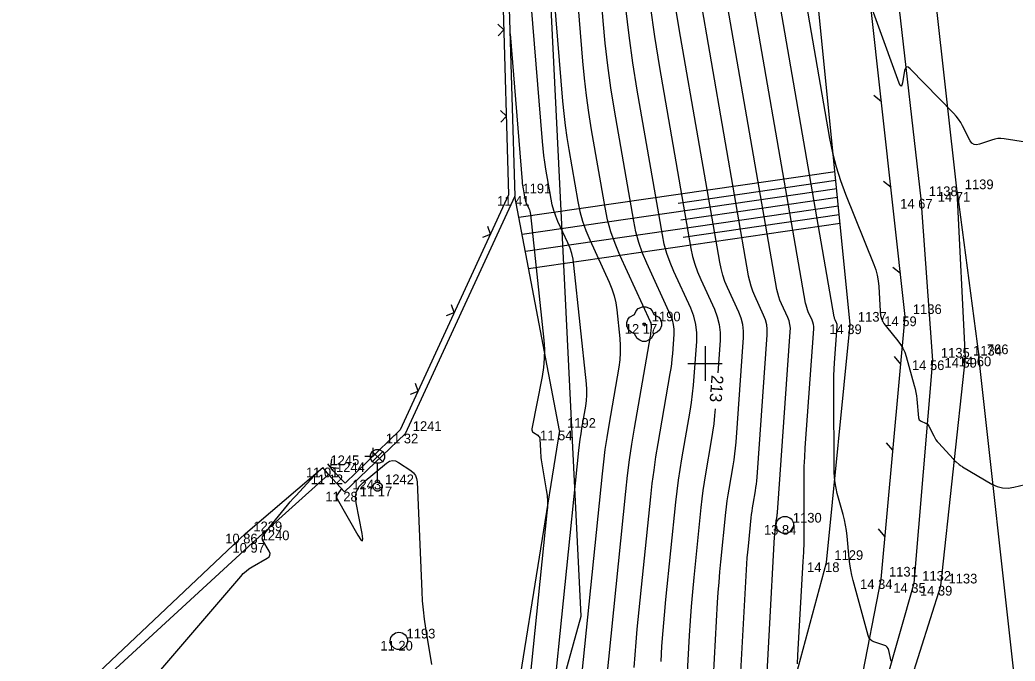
# Model space of a CAD drawing. Extents: x -711234 to -710007, y -1026313 to -1025448.
# Drawn here: x -710944.81 to -710916.03, y -1025833.6 to -1025815.07 of the extents above; entities that cross this region are included whole.
import ezdxf

# ---------------------------------------------------------------- set-up
doc = ezdxf.new("R2010")
doc.units = 0
for name, color, linetype in [('Ex_Contour Labels', 7, 'Continuous'), ('Ex_Major Contours', 7, 'Continuous'), ('Ex_Minor Contours', 7, 'Continuous'), ('Z_body', 7, 'Continuous'), ('Z_body_cisla', 7, 'Continuous'), ('Z_body_vysky_redukovane', 7, 'Continuous'), ('Z_hektometricka_sit', 7, 'Continuous'), ('Z_hrany_paty', 7, 'Continuous'), ('Z_katastr_hranice', 7, 'Continuous'), ('Z_komunikace', 7, 'Continuous'), ('Z_obruba', 7, 'Continuous'), ('Z_ploty', 7, 'Continuous'), ('Z_ploty_znacky', 7, 'Continuous'), ('Z_site_vo_znaky', 7, 'Continuous'), ('Z_svodidla', 7, 'Continuous'), ('Z_svodidla_znacky', 7, 'Continuous'), ('Z_technicke_srafy', 7, 'Continuous'), ('Z_vdz25_plna', 7, 'Continuous'), ('Z_vdz25_prerusovana', 7, 'Continuous'), ('Z_zelen_jednotliva', 7, 'Continuous')]:
    doc.layers.add(name, color=color, linetype=linetype)

# ---------------------------------------------------------------- blocks, each defined once
blk = doc.blocks.new('POINT_DISPLAY')
blk.add_line((0, 0), (0, 0))
blk = doc.blocks.new('Z10001')
blk.add_circle((0, 0), 0.25)
blk = doc.blocks.new('Z24')
for p, q in [((-0.28, 0.28), (-0.23, 0.38)), ((-0.23, 0.38), (-0.17, 0.45)), ((-0.17, 0.45), (-0.05, 0.5)), ((-0.05, 0.5), (0.05, 0.5)), ((0.05, 0.5), (0.17, 0.45)), ((0.17, 0.45), (0.23, 0.38)), ((0.23, 0.38), (0.28, 0.28)), ((-0.5, 0.05), (-0.47, 0.13)), ((-0.5, -0.05), (-0.5, 0.05)), ((-0.47, 0.13), (-0.42, 0.2)), ((-0.42, 0.2), (-0.28, 0.28)), ((-0.03, -0.03), (-0.03, 0.03)), ((-0.03, 0.03), (0.03, 0.03)), ((0.03, 0.03), (0.03, -0.03)), ((0.28, 0.28), (0.42, 0.2)), ((0.42, 0.2), (0.47, 0.13)), ((0.47, 0.13), (0.5, 0.05)), ((0.5, 0.05), (0.5, -0.05)), ((-0.45, -0.17), (-0.5, -0.05)), ((-0.38, -0.23), (-0.45, -0.17)), ((-0.28, -0.28), (-0.38, -0.23)), ((-0.2, -0.42), (-0.28, -0.28)), ((0.03, -0.03), (-0.03, -0.03)), ((0.28, -0.28), (0.2, -0.42)), ((0.38, -0.23), (0.28, -0.28)), ((0.45, -0.17), (0.38, -0.23)), ((0.5, -0.05), (0.45, -0.17)), ((-0.13, -0.47), (-0.2, -0.42)), ((-0.05, -0.5), (-0.13, -0.47)), ((0.05, -0.5), (-0.05, -0.5)), ((0.13, -0.47), (0.05, -0.5)), ((0.2, -0.42), (0.13, -0.47))]:
    blk.add_line(p, q)
blk = doc.blocks.new('Z34')
for p, q in [((-0.2, 0.93), (-0.15, 1.02)), ((-0.2, 0.82), (-0.2, 0.93)), ((-0.15, 1.02), (-0.05, 1.07)), ((0.15, 0.72), (-0.15, 1.02)), ((0.15, 1.02), (-0.15, 0.72)), ((-0.05, 1.07), (0.05, 1.07)), ((0.05, 1.07), (0.15, 1.02)), ((0.15, 1.02), (0.2, 0.93)), ((0.2, 0.93), (0.2, 0.82)), ((-0.15, 0.72), (-0.2, 0.82)), ((-0.05, 0.68), (-0.15, 0.72)), ((0.05, 0.68), (-0.05, 0.68)), ((0, 0.13), (0, 0.68)), ((0.15, 0.72), (0.05, 0.68)), ((0.2, 0.82), (0.15, 0.72)), ((-0.13, 0.03), (-0.1, 0.08)), ((-0.13, -0.03), (-0.13, 0.03)), ((-0.1, 0.08), (-0.08, 0.1)), ((-0.08, 0.1), (-0.03, 0.13)), ((-0.03, 0.13), (0.03, 0.13)), ((0.03, 0.13), (0.08, 0.1)), ((0.08, 0.1), (0.1, 0.08)), ((0.1, 0.08), (0.13, 0.03)), ((0.13, 0.03), (0.13, -0.03)), ((-0.1, -0.08), (-0.13, -0.03)), ((-0.08, -0.1), (-0.1, -0.08)), ((-0.03, -0.13), (-0.08, -0.1)), ((0.03, -0.13), (-0.03, -0.13)), ((0.08, -0.1), (0.03, -0.13)), ((0.1, -0.08), (0.08, -0.1)), ((0.13, -0.03), (0.1, -0.08))]:
    blk.add_line(p, q)
blk = doc.blocks.new('Z212')
for p, q in [((-0.17, 0.17), (0, 0)), ((0, 0), (0.17, 0.17))]:
    blk.add_line(p, q)
blk = doc.blocks.new('Z529')
blk.add_line((0, 0), (0.2, 0.2))

msp = doc.modelspace()

# ---------------------------------------------------------------- linework, layer by layer
at = {"layer": 'Ex_Major Contours'}
for points in [[(-710929.638, -1025811.052), (-710929.118, -1025817.417), (-710929.086, -1025817.767), (-710929.045, -1025818.117), (-710928.997, -1025818.465), (-710928.941, -1025818.813), (-710928.68, -1025820.315), (-710928.621, -1025820.602), (-710928.543, -1025820.883), (-710928.448, -1025821.159), (-710928.334, -1025821.429), (-710927.771, -1025822.653), (-710927.692, -1025822.845), (-710927.629, -1025823.041), (-710927.583, -1025823.242), (-710927.553, -1025823.447), (-710927.465, -1025824.276), (-710927.45, -1025824.484), (-710927.45, -1025824.69), (-710927.464, -1025824.896), (-710927.492, -1025825.102), (-710927.785, -1025826.787), (-710927.842, -1025827.137), (-710927.894, -1025827.488), (-710927.939, -1025827.839), (-710927.978, -1025828.192), (-710928.611, -1025834.404)], [(-710922.323, -1025833.681), (-710922.318, -1025833.429), (-710922.158, -1025830.726), (-710922.144, -1025830.452), (-710922.134, -1025830.178), (-710922.129, -1025829.904), (-710922.129, -1025829.629), (-710922.136, -1025828.532), (-710922.136, -1025828.257), (-710922.129, -1025827.983), (-710922.118, -1025827.709), (-710922.101, -1025827.435), (-710921.856, -1025824.001), (-710921.856, -1025823.935), (-710921.863, -1025823.871), (-710921.879, -1025823.809), (-710921.903, -1025823.747), (-710922.014, -1025823.505), (-710922.04, -1025823.444), (-710922.061, -1025823.382), (-710922.079, -1025823.318), (-710922.092, -1025823.253), (-710924.05, -1025811.969)], [(-710926.582, -1025814.654), (-710926.458, -1025815.549), (-710926.313, -1025816.441), (-710925.406, -1025821.672), (-710925.358, -1025821.903), (-710925.295, -1025822.13), (-710925.218, -1025822.353), (-710925.126, -1025822.571), (-710924.73, -1025823.433), (-710924.645, -1025823.651), (-710924.59, -1025823.874), (-710924.563, -1025824.103), (-710924.565, -1025824.337), (-710924.632, -1025825.268)], [(-710924.707, -1025826.315), (-710924.723, -1025826.504), (-710924.749, -1025826.746), (-710924.782, -1025826.988), (-710924.821, -1025827.229), (-710924.988, -1025828.192), (-710925.027, -1025828.433), (-710925.063, -1025828.674), (-710925.094, -1025828.916), (-710925.121, -1025829.159), (-710925.327, -1025831.184), (-710925.367, -1025831.603), (-710925.403, -1025832.022), (-710925.433, -1025832.442), (-710925.459, -1025832.861), (-710925.596, -1025835.349)], [(-710941.945, -1025835.27), (-710938.425, -1025831.155), (-710938.352, -1025831.076), (-710938.272, -1025831.004), (-710938.187, -1025830.939), (-710938.095, -1025830.882), (-710937.657, -1025830.632), (-710937.605, -1025830.592), (-710937.579, -1025830.545), (-710937.578, -1025830.492), (-710937.602, -1025830.431), (-710937.784, -1025830.114), (-710937.798, -1025830.081), (-710937.802, -1025830.048), (-710937.795, -1025830.015), (-710937.777, -1025829.984), (-710937.687, -1025829.857), (-710937.664, -1025829.826), (-710937.641, -1025829.795), (-710937.617, -1025829.764), (-710937.593, -1025829.734), (-710937.159, -1025829.198), (-710937.077, -1025829.099), (-710936.995, -1025829.002), (-710936.91, -1025828.906), (-710936.824, -1025828.812), (-710936.199, -1025828.137)]]:
    msp.add_lwpolyline(points, dxfattribs=at)
at = {"layer": 'Ex_Minor Contours'}
for points in [[(-710929.438, -1025835.264), (-710928.648, -1025827.511), (-710928.63, -1025827.35), (-710928.609, -1025827.19), (-710928.586, -1025827.03), (-710928.559, -1025826.87), (-710928.449, -1025826.232), (-710928.427, -1025826.073), (-710928.416, -1025825.913), (-710928.416, -1025825.752), (-710928.427, -1025825.591), (-710928.791, -1025822.152), (-710928.816, -1025821.986), (-710928.853, -1025821.823), (-710928.904, -1025821.663), (-710928.968, -1025821.507), (-710929.252, -1025820.891), (-710929.317, -1025820.736), (-710929.372, -1025820.577), (-710929.417, -1025820.415), (-710929.451, -1025820.249), (-710929.601, -1025819.384), (-710929.634, -1025819.183), (-710929.662, -1025818.983), (-710929.685, -1025818.781), (-710929.704, -1025818.579), (-710930.675, -1025806.688)], [(-710927.812, -1025833.833), (-710927.784, -1025833.545), (-710927.291, -1025828.703), (-710927.24, -1025828.243), (-710927.181, -1025827.785), (-710927.114, -1025827.328), (-710927.039, -1025826.872), (-710926.577, -1025824.207), (-710926.571, -1025824.173), (-710926.567, -1025824.138), (-710926.563, -1025824.104), (-710926.56, -1025824.069), (-710926.55, -1025823.93), (-710926.55, -1025823.895), (-710926.554, -1025823.862), (-710926.562, -1025823.829), (-710926.574, -1025823.797), (-710927.461, -1025821.869), (-710927.602, -1025821.534), (-710927.721, -1025821.192), (-710927.817, -1025820.842), (-710927.891, -1025820.486), (-710928.28, -1025818.242), (-710928.36, -1025817.747), (-710928.429, -1025817.251), (-710928.487, -1025816.753), (-710928.533, -1025816.254), (-710929.27, -1025807.237)], [(-710927.051, -1025833.791), (-710927.024, -1025833.422), (-710926.993, -1025833.053), (-710926.958, -1025832.685), (-710926.568, -1025828.855), (-710926.525, -1025828.468), (-710926.475, -1025828.081), (-710926.419, -1025827.696), (-710926.355, -1025827.312), (-710926.005, -1025825.291), (-710925.982, -1025825.149), (-710925.963, -1025825.007), (-710925.947, -1025824.865), (-710925.935, -1025824.721), (-710925.894, -1025824.148), (-710925.893, -1025824.006), (-710925.909, -1025823.868), (-710925.943, -1025823.733), (-710925.994, -1025823.6), (-710926.683, -1025822.103), (-710926.807, -1025821.807), (-710926.912, -1025821.505), (-710926.997, -1025821.196), (-710927.062, -1025820.881), (-710927.619, -1025817.671), (-710927.723, -1025817.029), (-710927.813, -1025816.385), (-710927.887, -1025815.74), (-710927.948, -1025815.092), (-710928.567, -1025807.512)], [(-710922.918, -1025809.733), (-710921.399, -1025818.492), (-710921.316, -1025818.904), (-710921.212, -1025819.309), (-710921.087, -1025819.709), (-710920.94, -1025820.102), (-710920.116, -1025822.142), (-710920.062, -1025822.295), (-710920.021, -1025822.45), (-710919.993, -1025822.608), (-710919.977, -1025822.769), (-710919.939, -1025823.483), (-710919.923, -1025823.609), (-710919.887, -1025823.728), (-710919.832, -1025823.84), (-710919.758, -1025823.943), (-710919.422, -1025824.343), (-710919.344, -1025824.446), (-710919.278, -1025824.556), (-710919.225, -1025824.672), (-710919.184, -1025824.795), (-710918.95, -1025825.637), (-710918.925, -1025825.735), (-710918.905, -1025825.834), (-710918.889, -1025825.933), (-710918.877, -1025826.033), (-710918.826, -1025826.567), (-710918.819, -1025826.599), (-710918.805, -1025826.626), (-710918.784, -1025826.648), (-710918.755, -1025826.665), (-710918.628, -1025826.722), (-710918.598, -1025826.738), (-710918.572, -1025826.758), (-710918.55, -1025826.783), (-710918.533, -1025826.812), (-710918.388, -1025827.096), (-710918.356, -1025827.152), (-710918.322, -1025827.206), (-710918.284, -1025827.258), (-710918.242, -1025827.307), (-710917.83, -1025827.761), (-710917.809, -1025827.783), (-710917.788, -1025827.804), (-710917.766, -1025827.824), (-710917.743, -1025827.843), (-710917.65, -1025827.919), (-710917.627, -1025827.938), (-710917.602, -1025827.955), (-710917.578, -1025827.972), (-710917.552, -1025827.987), (-710916.705, -1025828.485), (-710916.552, -1025828.557), (-710916.395, -1025828.597), (-710916.233, -1025828.605), (-710916.067, -1025828.58), (-710915.084, -1025828.345)], [(-710910.438, -1025819.427), (-710916.352, -1025818.505), (-710916.444, -1025818.496), (-710916.535, -1025818.499), (-710916.625, -1025818.513), (-710916.714, -1025818.538), (-710917.068, -1025818.662), (-710917.151, -1025818.678), (-710917.222, -1025818.666), (-710917.282, -1025818.626), (-710917.331, -1025818.557), (-710917.553, -1025818.125), (-710917.608, -1025818.028), (-710917.669, -1025817.935), (-710917.737, -1025817.848), (-710917.812, -1025817.765), (-710919.067, -1025816.479), (-710919.125, -1025816.433), (-710919.171, -1025816.426), (-710919.205, -1025816.458), (-710919.228, -1025816.528), (-710919.293, -1025816.887), (-710919.311, -1025816.955), (-710919.333, -1025816.979), (-710919.359, -1025816.959), (-710919.388, -1025816.895), (-710921.851, -1025810.091)], [(-710919.617, -1025833.609), (-710919.686, -1025833.299), (-710919.705, -1025833.244), (-710919.735, -1025833.199), (-710919.776, -1025833.165), (-710919.829, -1025833.141), (-710920.116, -1025833.045), (-710920.177, -1025833.017), (-710920.226, -1025832.978), (-710920.263, -1025832.927), (-710920.287, -1025832.864), (-710920.715, -1025831.277), (-710920.753, -1025831.12), (-710920.785, -1025830.962), (-710920.811, -1025830.803), (-710920.83, -1025830.642), (-710920.892, -1025829.989), (-710920.911, -1025829.832), (-710920.936, -1025829.677), (-710920.968, -1025829.523), (-710921.007, -1025829.37), (-710921.176, -1025828.761), (-710921.213, -1025828.608), (-710921.239, -1025828.454), (-710921.256, -1025828.298), (-710921.262, -1025828.141), (-710921.279, -1025825.717), (-710921.278, -1025825.532), (-710921.274, -1025825.347), (-710921.266, -1025825.162), (-710921.255, -1025824.977), (-710921.179, -1025823.917), (-710921.179, -1025823.893), (-710921.182, -1025823.87), (-710921.187, -1025823.848), (-710921.196, -1025823.826), (-710921.236, -1025823.739), (-710921.245, -1025823.717), (-710921.253, -1025823.695), (-710921.259, -1025823.672), (-710921.264, -1025823.649), (-710923.484, -1025810.851)], [(-710923.283, -1025835.371), (-710922.987, -1025830.012), (-710922.984, -1025829.967), (-710922.981, -1025829.922), (-710922.977, -1025829.877), (-710922.973, -1025829.832), (-710922.95, -1025829.615), (-710922.948, -1025829.589), (-710922.944, -1025829.563), (-710922.94, -1025829.537), (-710922.936, -1025829.512), (-710922.918, -1025829.408), (-710922.914, -1025829.383), (-710922.911, -1025829.357), (-710922.908, -1025829.331), (-710922.906, -1025829.305), (-710922.534, -1025824.085), (-710922.533, -1025823.977), (-710922.545, -1025823.872), (-710922.57, -1025823.769), (-710922.609, -1025823.669), (-710922.792, -1025823.272), (-710922.834, -1025823.171), (-710922.87, -1025823.069), (-710922.899, -1025822.965), (-710922.921, -1025822.858), (-710924.616, -1025813.087)], [(-710925.182, -1025814.205), (-710923.749, -1025822.463), (-710923.718, -1025822.611), (-710923.678, -1025822.756), (-710923.629, -1025822.899), (-710923.57, -1025823.038), (-710923.316, -1025823.59), (-710923.262, -1025823.73), (-710923.226, -1025823.873), (-710923.209, -1025824.019), (-710923.211, -1025824.169), (-710923.505, -1025828.29), (-710923.513, -1025828.388), (-710923.524, -1025828.487), (-710923.537, -1025828.584), (-710923.552, -1025828.682), (-710923.62, -1025829.072), (-710923.636, -1025829.169), (-710923.65, -1025829.267), (-710923.663, -1025829.365), (-710923.674, -1025829.463), (-710923.757, -1025830.283), (-710923.774, -1025830.452), (-710923.788, -1025830.622), (-710923.8, -1025830.792), (-710923.811, -1025830.962), (-710924.032, -1025834.958)], [(-710924.814, -1025835.153), (-710924.635, -1025831.912), (-710924.617, -1025831.617), (-710924.595, -1025831.322), (-710924.571, -1025831.028), (-710924.542, -1025830.734), (-710924.397, -1025829.311), (-710924.378, -1025829.141), (-710924.357, -1025828.971), (-710924.332, -1025828.801), (-710924.304, -1025828.632), (-710924.187, -1025827.955), (-710924.159, -1025827.786), (-710924.136, -1025827.616), (-710924.118, -1025827.446), (-710924.104, -1025827.275), (-710923.888, -1025824.253), (-710923.886, -1025824.061), (-710923.908, -1025823.874), (-710923.954, -1025823.69), (-710924.023, -1025823.511), (-710924.348, -1025822.804), (-710924.423, -1025822.626), (-710924.487, -1025822.443), (-710924.538, -1025822.257), (-710924.577, -1025822.067), (-710925.747, -1025815.323), (-710925.871, -1025814.558)], [(-710926.272, -1025833.621), (-710926.245, -1025833.171), (-710926.212, -1025832.722), (-710926.174, -1025832.273), (-710926.131, -1025831.825), (-710925.844, -1025829.007), (-710925.809, -1025828.692), (-710925.769, -1025828.378), (-710925.723, -1025828.064), (-710925.672, -1025827.752), (-710925.433, -1025826.375), (-710925.393, -1025826.126), (-710925.359, -1025825.876), (-710925.332, -1025825.626), (-710925.311, -1025825.374), (-710925.239, -1025824.366), (-710925.236, -1025824.117), (-710925.265, -1025823.874), (-710925.324, -1025823.636), (-710925.414, -1025823.404), (-710925.904, -1025822.337), (-710926.013, -1025822.08), (-710926.104, -1025821.818), (-710926.177, -1025821.55), (-710926.234, -1025821.277), (-710926.959, -1025817.1), (-710927.086, -1025816.311), (-710927.196, -1025815.519), (-710927.288, -1025814.726)], [(-710930.638, -1025815.466), (-710930.289, -1025819.742), (-710930.284, -1025819.795), (-710930.278, -1025819.848), (-710930.271, -1025819.901), (-710930.262, -1025819.954), (-710930.222, -1025820.184), (-710930.213, -1025820.227), (-710930.202, -1025820.27), (-710930.187, -1025820.312), (-710930.17, -1025820.354), (-710930.095, -1025820.517), (-710930.078, -1025820.558), (-710930.064, -1025820.6), (-710930.054, -1025820.643), (-710930.048, -1025820.687), (-710929.663, -1025824.321), (-710929.645, -1025824.587), (-710929.647, -1025824.852), (-710929.669, -1025825.116), (-710929.71, -1025825.379), (-710930.007, -1025826.885), (-710930.009, -1025826.919), (-710930.002, -1025826.949), (-710929.986, -1025826.974), (-710929.96, -1025826.996), (-710929.839, -1025827.075), (-710929.813, -1025827.097), (-710929.793, -1025827.123), (-710929.781, -1025827.153), (-710929.776, -1025827.187), (-710929.762, -1025827.52), (-710929.758, -1025827.588), (-710929.752, -1025827.655), (-710929.744, -1025827.722), (-710929.734, -1025827.789), (-710929.591, -1025828.65), (-710929.569, -1025828.816), (-710929.559, -1025828.983), (-710929.559, -1025829.15), (-710929.57, -1025829.317), (-710930.264, -1025836.124)], [(-710935.508, -1025828.616), (-710935.635, -1025828.794), (-710935.651, -1025828.824), (-710935.658, -1025828.854), (-710935.654, -1025828.885), (-710935.641, -1025828.916), (-710935.042, -1025829.96), (-710934.955, -1025830.094), (-710934.904, -1025830.131), (-710934.891, -1025830.07), (-710934.914, -1025829.912), (-710935.09, -1025829.025), (-710935.104, -1025828.855), (-710935.073, -1025828.7), (-710934.999, -1025828.561), (-710934.882, -1025828.438), (-710934.207, -1025827.879), (-710934.124, -1025827.827), (-710934.04, -1025827.807), (-710933.954, -1025827.818), (-710933.866, -1025827.86), (-710933.51, -1025828.093), (-710933.432, -1025828.158), (-710933.375, -1025828.234), (-710933.339, -1025828.322), (-710933.324, -1025828.422), (-710933.19, -1025831.594), (-710933.175, -1025831.86), (-710933.152, -1025832.124), (-710933.12, -1025832.388), (-710933.081, -1025832.651), (-710932.907, -1025833.701)]]:
    msp.add_lwpolyline(points, dxfattribs=at)
at = {"layer": 'Z_hektometricka_sit'}
for p, q in [((-710925, -1025824.5), (-710925, -1025825.5)), ((-710925.5, -1025825), (-710924.5, -1025825))]:
    msp.add_line(p, q, dxfattribs=at)
at = {"layer": 'Z_hrany_paty'}
for p, q in [((-710920.8, -1025823.87), (-710922.33, -1025808.57)), ((-710929.21, -1025826.94), (-710930.5, -1025820.16)), ((-710921.49, -1025830.75), (-710920.8, -1025823.87)), ((-710929.21, -1025826.94), (-710930.76, -1025836.64)), ((-710922.92, -1025836.06), (-710921.49, -1025830.75))]:
    msp.add_line(p, q, dxfattribs=at)
at = {"layer": 'Z_katastr_hranice'}
msp.add_lwpolyline([(-710937.26, -1025842.82), (-710936.45, -1025842.11), (-710935.96, -1025842), (-710933.08, -1025840.66), (-710931.05, -1025838.78), (-710930.88, -1025838.46), (-710929.59, -1025835.96), (-710928.58, -1025832.31), (-710932.7, -1025748.89), (-710932.82, -1025746.51)], dxfattribs=at)
at = {"layer": 'Z_komunikace'}
for p, q in [((-710918.75, -1025820.24), (-710920.14, -1025808.08)), ((-710918.41, -1025824.91), (-710918.75, -1025820.24)), ((-710918.95, -1025831.35), (-710918.41, -1025824.91)), ((-710938.29, -1025829.92), (-710936.05, -1025828.01)), ((-710944.81, -1025836.08), (-710938.29, -1025829.92)), ((-710920.92, -1025838.27), (-710918.95, -1025831.35))]:
    msp.add_line(p, q, dxfattribs=at)
at = {"layer": 'Z_obruba'}
for p, q in [((-710938.08, -1025830.19), (-710935.89, -1025828.21)), ((-710944.71, -1025836.26), (-710938.08, -1025830.19))]:
    msp.add_line(p, q, dxfattribs=at)
at = {"layer": 'Z_ploty'}
for p, q in [((-710931.07, -1025806.61), (-710930.68, -1025820.12)), ((-710930.9, -1025806.6), (-710930.5, -1025820.16)), ((-710930.68, -1025820.12), (-710933.812, -1025826.921)), ((-710930.5, -1025820.16), (-710933.67, -1025827.03)), ((-710933.812, -1025826.921), (-710935.41, -1025828.46)), ((-710933.67, -1025827.03), (-710935.42, -1025828.71)), ((-710935.89, -1025828.21), (-710936.05, -1025828.01)), ((-710935.75, -1025828.1), (-710935.91, -1025827.9)), ((-710935.41, -1025828.46), (-710935.76, -1025828.09)), ((-710935.42, -1025828.71), (-710935.89, -1025828.21))]:
    msp.add_line(p, q, dxfattribs=at)
at = {"layer": 'Z_svodidla'}
for p, q in [((-710919.21, -1025823.64), (-710920.91, -1025808.34)), ((-710919.91, -1025831.24), (-710919.21, -1025823.64)), ((-710920.78, -1025835.74), (-710919.91, -1025831.24))]:
    msp.add_line(p, q, dxfattribs=at)
at = {"layer": 'Z_technicke_srafy'}
for p, q in [((-710921.24, -1025819.46), (-710930.38, -1025820.78)), ((-710921.22, -1025819.71), (-710925.78, -1025820.37)), ((-710921.19, -1025819.95), (-710930.29, -1025821.27)), ((-710921.17, -1025820.2), (-710925.7, -1025820.86)), ((-710921.14, -1025820.45), (-710930.19, -1025821.76)), ((-710921.09, -1025820.95), (-710930.1, -1025822.26)), ((-710921.12, -1025820.7), (-710925.63, -1025821.36))]:
    msp.add_line(p, q, dxfattribs=at)
at = {"layer": 'Z_vdz25_plna'}
for p, q in [((-710917.71, -1025820.04), (-710919.06, -1025808)), ((-710917.47, -1025824.84), (-710917.71, -1025820.04)), ((-710918.18, -1025831.43), (-710917.47, -1025824.84)), ((-710920.4, -1025838.38), (-710918.18, -1025831.43))]:
    msp.add_line(p, q, dxfattribs=at)
at = {"layer": 'Z_vdz25_prerusovana'}
for p in [(-710917.71, -1025820.04), (-710915.25, -1025841.32)]:
    msp.add_line(p, (-710917.08, -1025824.8), dxfattribs=at)

# ---------------------------------------------------------------- block references
at = {"layer": 'Z_body'}
for p in [(-710917.71, -1025820.04), (-710930.5, -1025820.16), (-710918.75, -1025820.24), (-710919.21, -1025823.64), (-710926.76, -1025823.86), (-710920.8, -1025823.87), (-710918.41, -1025824.91), (-710917.47, -1025824.84), (-710917.08, -1025824.8), (-710929.21, -1025826.94), (-710933.67, -1025827.03), (-710936.05, -1025828.01), (-710935.89, -1025828.21), (-710935.42, -1025828.71), (-710934.47, -1025828.56), (-710922.69, -1025829.67), (-710938.29, -1025829.92), (-710938.08, -1025830.19), (-710921.49, -1025830.75), (-710919.91, -1025831.24), (-710918.95, -1025831.35), (-710918.18, -1025831.43), (-710933.85, -1025833.02)]:
    msp.add_blockref('POINT_DISPLAY', p, dxfattribs=at)
at = {"layer": 'Z_ploty_znacky'}
for p, rotation in [((-710930.82, -1025815.35), 91.7), ((-710930.74, -1025817.85), 91.7), ((-710931.2, -1025821.26), 65.2), ((-710932.25, -1025823.53), 65.2), ((-710933.29, -1025825.8), 65.2), ((-710934.6, -1025827.68), 43.8), ((-710935.83, -1025828), -51.30000000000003)]:
    msp.add_blockref('Z212', p, dxfattribs=dict(at, rotation=rotation))
at = {"layer": 'Z_site_vo_znaky'}
msp.add_blockref('Z34', (-710934.47, -1025828.56), dxfattribs=at)
at = {"layer": 'Z_svodidla_znacky'}
for p, rotation in [((-710919.9, -1025817.43), 96.3), ((-710919.62, -1025819.91), 96.3), ((-710919.35, -1025822.4), 96.3), ((-710919.34, -1025825.02), 84.7), ((-710919.57, -1025827.51), 84.7), ((-710919.8, -1025830), 84.7)]:
    msp.add_blockref('Z529', p, dxfattribs=dict(at, rotation=rotation))
at = {"layer": 'Z_zelen_jednotliva'}
for name, p in [('Z24', (-710926.76, -1025823.86)), ('Z10001', (-710922.69, -1025829.67)), ('Z10001', (-710933.85, -1025833.02))]:
    msp.add_blockref(name, p, dxfattribs=at)

# ---------------------------------------------------------------- texts
at = {"layer": 'Ex_Contour Labels'}
msp.add_text('213', height=0.35, rotation=265.8867, dxfattribs=at).set_placement((-710924.812, -1025825.328))
at = {"layer": 'Z_body_cisla'}
for s, p in [('1191', (-710930.28, -1025820.08)), ('1139', (-710917.49, -1025819.96)), ('1138', (-710918.53, -1025820.16)), ('1190', (-710926.54, -1025823.78)), ('1137', (-710920.58, -1025823.79)), ('1136', (-710918.99, -1025823.57)), ('1135', (-710918.18, -1025824.83)), ('1134', (-710917.25, -1025824.77)), ('766', (-710916.85, -1025824.73)), ('1241', (-710933.45, -1025826.95)), ('1192', (-710928.99, -1025826.86)), ('1245', (-710935.83, -1025827.94)), ('1244', (-710935.67, -1025828.14)), ('1243', (-710935.2, -1025828.64)), ('1242', (-710934.25, -1025828.49)), ('1239', (-710938.06, -1025829.85)), ('1130', (-710922.46, -1025829.6)), ('1240', (-710937.85, -1025830.11)), ('1129', (-710921.26, -1025830.68)), ('1131', (-710919.68, -1025831.16)), ('1132', (-710918.72, -1025831.28)), ('1133', (-710917.96, -1025831.36)), ('1193', (-710933.63, -1025832.95))]:
    msp.add_text(s, height=0.28, dxfattribs=at).set_placement(p)
at = {"layer": 'Z_body_vysky_redukovane'}
for s, p in [('14 71', (-710918.27, -1025820.32)), ('11 41', (-710931.013, -1025820.44)), ('14 67', (-710919.357, -1025820.52)), ('14 59', (-710919.817, -1025823.92)), ('12 17', (-710927.32, -1025824.14)), ('14 39', (-710921.407, -1025824.15)), ('14 56', (-710919.017, -1025825.19)), ('14 59', (-710918.077, -1025825.12)), ('14 60', (-710917.663, -1025825.08)), ('11 54', (-710929.77, -1025827.22)), ('11 32', (-710934.23, -1025827.31)), ('11 01', (-710936.54, -1025828.29)), ('11 12', (-710936.403, -1025828.49)), ('11 28', (-710935.98, -1025828.99)), ('11 17', (-710934.983, -1025828.84)), ('13 84', (-710923.297, -1025829.95)), ('10 86', (-710938.873, -1025830.2)), ('10 97', (-710938.663, -1025830.47)), ('14 18', (-710922.05, -1025831.03)), ('14 34', (-710920.517, -1025831.52)), ('14 35', (-710919.557, -1025831.63)), ('14 39', (-710918.787, -1025831.71)), ('11 20', (-710934.387, -1025833.3))]:
    msp.add_text(s, height=0.28, dxfattribs=at).set_placement(p)

doc.saveas('drawing.dxf')
